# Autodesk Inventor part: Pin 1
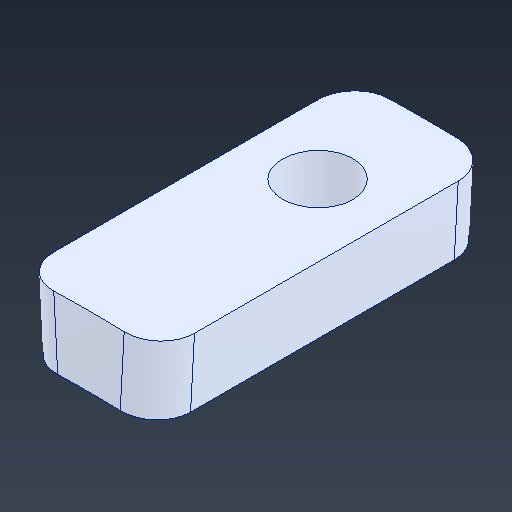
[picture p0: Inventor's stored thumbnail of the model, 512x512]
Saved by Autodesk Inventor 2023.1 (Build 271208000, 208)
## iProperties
Created: 2020-02
Part Number: Pin 1
Material: SOLIDWORKS Materials|6061 Alloy
Document SubType Name: Modeling
Designer: ftrauzettel
Density: 2.7 g/cm^3
Appearance: 221,232,255
Sending System: SolidWorks 2016
Last Author: Pam
Last Saved: 2020-02-18
Author: ftrauzettel
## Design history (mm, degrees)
fillet "Fillet1"
body "Solid1"
